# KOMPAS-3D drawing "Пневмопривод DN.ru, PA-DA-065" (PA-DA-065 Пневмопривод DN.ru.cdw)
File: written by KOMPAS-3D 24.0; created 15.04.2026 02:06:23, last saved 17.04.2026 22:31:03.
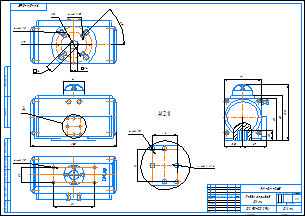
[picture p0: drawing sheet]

Document properties: Автор: DN.ru; Форматы листов документа: A2; Полное имя файла: PA-DA-065 Пневмопривод DN.ru.m3d; Масса: 2; Наименование: Пневмопривод DN.ru; Количество листов документа: 1; Примечание: D290-00294

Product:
- Part/product: Пневмопривод DN.ru  | designation PA-DA-065
    Масса: 2
    Раздел спецификации: Прочие изделия
    Примечание: D290-00294

Views: Вид 1, Вид:1, Проекционный вид 2, Выносной элемент 6, Выносной элемент А, Выносной элемент
Referenced files in C:\Работа\PA-DA-х Пневмопривод DN.ru\052\: PA-DA-052 Пневмопривод DN.ru.m3d
Referenced files in C:\Работа\PA-DA-х Пневмопривод DN.ru\065\: PA-DA-065 Пневмопривод DN.ru.m3d
Referenced files in C:\Program Files\ASCON\KOMPAS-3D v24\Templates\: Чертеж_DN.ru.cdt
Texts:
  objid
  viewid
  PA-DA-065
  Чертеж_DN.ru.cdt
  Пневмопривод
  Пневмопривод DN.ru
  PA-DA-065 Пневмопривод DN.ru
Dimensions and other numbers on the sheet: 0; 3; 2; 4; 40; 608; 168; 9; 4 отв.; 6; 14; 50; 70; 8; 7; 1; 2 отв.; 24; 32; 5; 1:1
